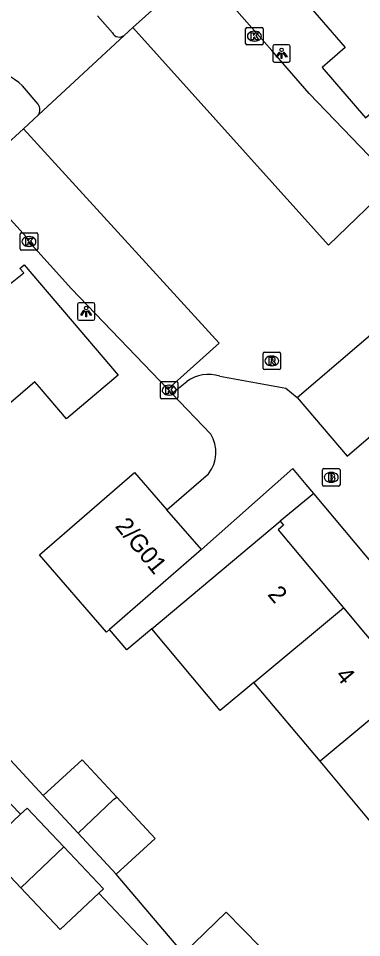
# Model space of a CAD drawing. Extents: x 157466 to 158888, y 383063 to 384677.
# Drawn here: x 158011.8 to 158031.4, y 383626.4 to 383679.1 of the extents above; entities that cross this region are included whole.
import ezdxf

# ---------------------------------------------------------------- set-up
doc = ezdxf.new("R2010")
doc.units = 0
for name, color, linetype in [('IMGEO_Brandkraan', 7, 'Continuous'), ('IMGEO_Kolk', 7, 'Continuous'), ('IMGEO_Lichtpunt', 7, 'Continuous'), ('IMGEO_Pand', 7, 'Continuous'), ('IMGEO_Pand_nummerreeks', 7, 'Continuous'), ('IMGEO_Parkeervlak_open', 7, 'Continuous'), ('IMGEO_Rijbaan_lokaal_open', 7, 'Continuous'), ('IMGEO_Rioolput', 7, 'Continuous'), ('IMGEO_Voetpad_open', 7, 'Continuous')]:
    doc.layers.add(name, color=color, linetype=linetype)

msp = doc.modelspace()

# ---------------------------------------------------------------- linework, layer by layer
at = {"layer": 'IMGEO_Brandkraan'}
for p, q in [((158029.199, 383652.369), (158029.199, 383653.221)), ((158029.274, 383653.295), (158030.126, 383653.295)), ((158029.687, 383653.075), (158029.712, 383653.075)), ((158030.2, 383653.221), (158030.2, 383652.369)), ((158029.71, 383652.515), (158029.685, 383652.515)), ((158030.126, 383652.295), (158029.274, 383652.295))]:
    msp.add_line(p, q, dxfattribs=at)
for points in [[(158029.199, 383652.369), (158029.199, 383653.221)], [(158029.274, 383653.295), (158030.126, 383653.295)], [(158029.547, 383652.995), (158029.547, 383652.595), (158029.76, 383652.595)], [(158029.778, 383652.995), (158029.547, 383652.995)], [(158030.2, 383653.221), (158030.2, 383652.369)], [(158029.726, 383652.914), (158029.672, 383652.914), (158029.672, 383652.838)], [(158029.672, 383652.838), (158029.725, 383652.838)], [(158029.734, 383652.762), (158029.672, 383652.762), (158029.672, 383652.681)], [(158029.672, 383652.681), (158029.734, 383652.681)], [(158030.126, 383652.295), (158029.274, 383652.295)]]:
    msp.add_lwpolyline(points, dxfattribs=at)
for centre, radius, start, end in [((158029.276, 383653.219), 0.0765, 91.552, 178.448), ((158029.276, 383653.219), 0.0765, 91.552, 178.448), ((158029.782, 383652.85), 0.145, 59.4692, 91.5367), ((158029.807, 383652.897), 0.0922, 285.5137, 58.1501), ((158030.124, 383653.219), 0.0765, 1.552, 88.448), ((158030.124, 383653.219), 0.0765, 1.552, 88.448), ((158029.727, 383652.876), 0.0379, 267.8285, 90.9355), ((158029.735, 383652.721), 0.0404, 269.8759, 90.5077), ((158029.766, 383652.846), 0.251, 268.6676, 293.5347), ((158029.812, 383652.705), 0.105, 301.3115, 78.989), ((158029.276, 383652.371), 0.0765, 181.552, 268.448), ((158029.276, 383652.371), 0.0765, 181.552, 268.448), ((158030.124, 383652.371), 0.0765, 271.552, 358.448), ((158030.124, 383652.371), 0.0765, 271.552, 358.448)]:
    msp.add_arc(centre, radius, start, end, dxfattribs=at)
for centre, major_axis, ratio, start_param, end_param in [((158029.686, 383652.795), (-0.387, 0.002), 0.722429, 4.712389, 7.853982), ((158029.711, 383652.795), (-0.39, 0.002), 0.717154, 1.570796, 4.712389)]:
    msp.add_ellipse(centre, major_axis=major_axis, ratio=ratio, start_param=start_param, end_param=end_param, dxfattribs=at)
at = {"layer": 'IMGEO_Kolk'}
for p, q in [((158024.794, 383677.639), (158024.794, 383678.491)), ((158024.869, 383678.565), (158025.721, 383678.565)), ((158025.282, 383678.345), (158025.307, 383678.345)), ((158025.795, 383678.491), (158025.795, 383677.639)), ((158025.305, 383677.785), (158025.28, 383677.785)), ((158025.721, 383677.565), (158024.869, 383677.565)), ((158011.88, 383665.877), (158011.88, 383666.729)), ((158011.955, 383666.803), (158012.807, 383666.803)), ((158012.881, 383666.729), (158012.881, 383665.877)), ((158012.368, 383666.583), (158012.393, 383666.583)), ((158012.807, 383665.803), (158011.955, 383665.803)), ((158012.391, 383666.023), (158012.366, 383666.023)), ((158019.908, 383657.361), (158019.908, 383658.213)), ((158019.983, 383658.287), (158020.835, 383658.287)), ((158020.909, 383658.213), (158020.909, 383657.361)), ((158020.396, 383658.067), (158020.421, 383658.067)), ((158020.835, 383657.287), (158019.983, 383657.287)), ((158020.419, 383657.507), (158020.394, 383657.507))]:
    msp.add_line(p, q, dxfattribs=at)
for points in [[(158024.794, 383677.639), (158024.794, 383678.491)], [(158024.869, 383678.565), (158025.721, 383678.565)], [(158025.115, 383678.265), (158025.238, 383678.265), (158025.238, 383678.114), (158025.368, 383678.265), (158025.532, 383678.265), (158025.386, 383678.114), (158025.539, 383677.865), (158025.387, 383677.865), (158025.302, 383678.029), (158025.238, 383677.962), (158025.238, 383677.865), (158025.115, 383677.865), (158025.115, 383678.265)], [(158025.795, 383678.491), (158025.795, 383677.639)], [(158025.721, 383677.565), (158024.869, 383677.565)], [(158011.88, 383665.877), (158011.88, 383666.729)], [(158011.955, 383666.803), (158012.807, 383666.803)], [(158012.881, 383666.729), (158012.881, 383665.877)], [(158012.201, 383666.503), (158012.324, 383666.503), (158012.324, 383666.352), (158012.454, 383666.503), (158012.618, 383666.503), (158012.472, 383666.352), (158012.625, 383666.103), (158012.473, 383666.103), (158012.388, 383666.267), (158012.324, 383666.2), (158012.324, 383666.103), (158012.201, 383666.103), (158012.201, 383666.503)], [(158012.807, 383665.803), (158011.955, 383665.803)], [(158019.908, 383657.361), (158019.908, 383658.213)], [(158019.983, 383658.287), (158020.835, 383658.287)], [(158020.909, 383658.213), (158020.909, 383657.361)], [(158020.229, 383657.987), (158020.352, 383657.987), (158020.352, 383657.836), (158020.482, 383657.987), (158020.646, 383657.987), (158020.5, 383657.836), (158020.653, 383657.587), (158020.501, 383657.587), (158020.416, 383657.751), (158020.352, 383657.684), (158020.352, 383657.587), (158020.229, 383657.587), (158020.229, 383657.987)], [(158020.835, 383657.287), (158019.983, 383657.287)]]:
    msp.add_lwpolyline(points, dxfattribs=at)
for centre, start, end in [((158024.871, 383678.489), 91.552, 178.448), ((158024.871, 383678.489), 91.552, 178.448), ((158025.719, 383678.489), 1.552, 88.448), ((158025.719, 383678.489), 1.552, 88.448), ((158024.871, 383677.641), 181.552, 268.448), ((158024.871, 383677.641), 181.552, 268.448), ((158025.719, 383677.641), 271.552, 358.448), ((158025.719, 383677.641), 271.552, 358.448), ((158011.957, 383666.727), 91.552, 178.448), ((158011.957, 383666.727), 91.552, 178.448), ((158012.805, 383666.727), 1.552, 88.448), ((158012.805, 383666.727), 1.552, 88.448), ((158011.957, 383665.879), 181.552, 268.448), ((158011.957, 383665.879), 181.552, 268.448), ((158012.805, 383665.879), 271.552, 358.448), ((158012.805, 383665.879), 271.552, 358.448), ((158019.985, 383658.211), 91.552, 178.448), ((158019.985, 383658.211), 91.552, 178.448), ((158020.833, 383658.211), 1.552, 88.448), ((158020.833, 383658.211), 1.552, 88.448), ((158019.985, 383657.363), 181.552, 268.448), ((158019.985, 383657.363), 181.552, 268.448), ((158020.833, 383657.363), 271.552, 358.448), ((158020.833, 383657.363), 271.552, 358.448)]:
    msp.add_arc(centre, 0.0765, start, end, dxfattribs=at)
for centre, major_axis, ratio, start_param, end_param in [((158025.281, 383678.065), (-0.387, 0.002), 0.722429, 4.712389, 7.853982), ((158025.306, 383678.065), (-0.39, 0.002), 0.717154, 1.570796, 4.712389), ((158012.367, 383666.303), (-0.387, 0.002), 0.722429, 4.712389, 7.853982), ((158012.392, 383666.303), (-0.39, 0.002), 0.717154, 1.570796, 4.712389), ((158020.395, 383657.787), (-0.387, 0.002), 0.722429, 4.712389, 7.853982), ((158020.42, 383657.787), (-0.39, 0.002), 0.717154, 1.570796, 4.712389)]:
    msp.add_ellipse(centre, major_axis=major_axis, ratio=ratio, start_param=start_param, end_param=end_param, dxfattribs=at)
at = {"layer": 'IMGEO_Lichtpunt'}
for p, q in [((158026.353, 383677.484), (158026.353, 383676.677)), ((158026.353, 383677.484), (158026.353, 383676.677)), ((158027.255, 383677.579), (158026.447, 383677.579)), ((158027.255, 383677.579), (158026.447, 383677.579)), ((158027.349, 383676.677), (158027.349, 383677.484)), ((158027.349, 383676.677), (158027.349, 383677.484)), ((158026.447, 383676.583), (158027.255, 383676.583)), ((158026.447, 383676.583), (158027.255, 383676.583)), ((158015.157, 383662.698), (158015.157, 383661.891)), ((158015.157, 383662.698), (158015.157, 383661.891)), ((158016.059, 383662.793), (158015.251, 383662.793)), ((158016.059, 383662.793), (158015.251, 383662.793)), ((158016.153, 383661.891), (158016.153, 383662.698)), ((158016.153, 383661.891), (158016.153, 383662.698)), ((158015.251, 383661.797), (158016.059, 383661.797)), ((158015.251, 383661.797), (158016.059, 383661.797))]:
    msp.add_line(p, q, dxfattribs=at)
for points in [[(158026.727, 383677.148), (158026.766, 383677.12), (158026.578, 383676.858), (158026.54, 383676.885), (158026.727, 383677.148)], [(158026.829, 383677.1), (158026.876, 383677.1), (158026.876, 383676.778), (158026.829, 383676.778), (158026.829, 383677.1)], [(158026.939, 383677.12), (158026.977, 383677.147), (158027.164, 383676.885), (158027.125, 383676.857), (158026.939, 383677.12)], [(158015.531, 383662.362), (158015.57, 383662.334), (158015.382, 383662.072), (158015.344, 383662.099), (158015.531, 383662.362)], [(158015.633, 383662.314), (158015.68, 383662.314), (158015.68, 383661.992), (158015.633, 383661.992), (158015.633, 383662.314)], [(158015.743, 383662.334), (158015.781, 383662.361), (158015.968, 383662.099), (158015.929, 383662.071), (158015.743, 383662.334)]]:
    msp.add_lwpolyline(points, dxfattribs=at)
for centre in [(158026.852, 383677.282), (158015.656, 383662.496)]:
    msp.add_circle(centre, 0.0994, dxfattribs=at)
for centre, start, end in [((158026.447, 383677.484), 90, 180), ((158026.447, 383677.484), 90, 180), ((158027.255, 383677.484), 0, 90), ((158027.255, 383677.484), 0, 90), ((158026.447, 383676.677), 180, 270), ((158026.447, 383676.677), 180, 270), ((158027.255, 383676.677), 270, 0), ((158027.255, 383676.677), 270, 360), ((158015.251, 383662.698), 90, 180), ((158015.251, 383662.698), 90, 180), ((158016.059, 383662.698), 0, 90), ((158016.059, 383662.698), 0, 90), ((158015.251, 383661.891), 180, 270), ((158015.251, 383661.891), 180, 270), ((158016.059, 383661.891), 270, 0), ((158016.059, 383661.891), 270, 360)]:
    msp.add_arc(centre, 0.0946, start, end, dxfattribs=at)
at = {"layer": 'IMGEO_Pand'}
for points in [[(158031.569, 383685.38), (158027.267, 383681.66), (158027.02, 383681.945), (158026.766, 383681.725), (158030.495, 383677.414), (158029.171, 383676.269), (158031.662, 383673.388), (158037.565, 383678.493)], [(158003.932, 383659.572), (158008.317, 383663.337), (158008.105, 383663.584), (158008.353, 383663.735), (158009.559, 383662.338), (158010.633, 383663.362), (158012.09, 383664.505), (158011.854, 383664.762), (158012.101, 383664.966), (158017.498, 383658.647), (158014.531, 383656.155), (158012.982, 383657.958), (158012.714, 383658.27), (158008.303, 383654.494)], [(158016.985, 383644.072), (158016.818, 383643.927), (158012.979, 383648.347), (158018.42, 383653.074), (158020.282, 383650.931)], [(158022.26, 383648.654), (158020.282, 383650.931)], [(158019.411, 383644.12), (158026.769, 383650.288)], [(158026.769, 383650.288), (158026.969, 383650.049), (158026.649, 383649.78), (158030.391, 383645.317)], [(158022.26, 383648.654), (158016.985, 383644.072)], [(158025.272, 383641.046), (158030.391, 383645.317)], [(158030.391, 383645.317), (158034.176, 383640.801)], [(158025.272, 383641.046), (158023.34, 383639.434), (158019.411, 383644.12)], [(158029.056, 383636.532), (158025.272, 383641.046)], [(158034.176, 383640.801), (158029.056, 383636.532)], [(158013.201, 383634.565), (158015.42, 383636.623), (158017.405, 383634.483)], [(158032.886, 383631.963), (158029.056, 383636.532)], [(158015.199, 383632.411), (158013.201, 383634.565)], [(158015.199, 383632.411), (158017.231, 383634.338), (158017.405, 383634.483)], [(158017.405, 383634.483), (158019.601, 383632.116), (158017.382, 383630.057)], [(158011.897, 383633.502), (158009.801, 383631.523), (158011.909, 383629.29)], [(158011.897, 383633.502), (158012.268, 383633.852), (158014.371, 383631.626)], [(158017.382, 383630.057), (158015.199, 383632.411)], [(158014.371, 383631.626), (158011.909, 383629.29)], [(158014.371, 383631.626), (158016.642, 383629.221), (158016.386, 383628.979)], [(158011.909, 383629.29), (158014.175, 383626.891), (158016.386, 383628.979)], [(158021.234, 383625.516), (158023.679, 383627.897), (158025.621, 383625.902)]]:
    msp.add_lwpolyline(points, dxfattribs=at)
at = {"layer": 'IMGEO_Parkeervlak_open'}
for points in [[(158033.301, 383669.722), (158028.432, 383674.777), (158026.297, 383677.24), (158022.137, 383681.981)], [(158020.339, 383657.837), (158014.816, 383663.599), (158012.381, 383666.302), (158012.232, 383666.546), (158009.061, 383670.029)]]:
    msp.add_lwpolyline(points, dxfattribs=at)
at = {"layer": 'IMGEO_Rijbaan_lokaal_open'}
for points in [[(158016.305, 383679.228), (158017.167, 383678.253)], [(158017.829, 383678.113), (158018.338, 383678.57)], [(158033.301, 383669.722), (158029.537, 383666.096), (158018.338, 383678.57)], [(158012.919, 383673.553), (158017.829, 383678.113)], [(158012.91, 383674.169), (158012.009, 383675.219)], [(158012.059, 383672.767), (158012.919, 383673.553)], [(158020.339, 383657.837), (158023.282, 383660.48), (158012.059, 383672.767)], [(158027.75, 383657.373), (158033.669, 383662.438)], [(158027.75, 383657.373), (158030.605, 383654.01), (158036.509, 383659.061), (158033.669, 383662.438)], [(158020.569, 383657.597), (158021.424, 383658.284)], [(158023.307, 383658.59), (158027.089, 383657.911), (158027.75, 383657.373)], [(158020.569, 383657.597), (158020.339, 383657.837)], [(158022.792, 383655.277), (158020.569, 383657.597)], [(158020.282, 383650.931), (158022.662, 383652.998)], [(158028.7, 383651.869), (158028.264, 383652.389), (158027.495, 383653.306), (158022.26, 383648.654)], [(158050.108, 383626.331), (158028.7, 383651.869)]]:
    msp.add_lwpolyline(points, dxfattribs=at)
for centre, radius, start, end in [((158017.551, 383678.435), 0.425, 205.3272, 310.7908), ((158009.964, 383673.189), 2.881, 44.801, 134.6074), ((158012.471, 383673.855), 0.54, 326.0463, 35.6278), ((158022.666, 383656.589), 2.102, 72.2383, 126.2222), ((158021.125, 383654.229), 1.969, 321.3057, 32.1648)]:
    msp.add_arc(centre, radius, start, end, dxfattribs=at)
at = {"layer": 'IMGEO_Rioolput'}
for p, q in [((158025.794, 383659.039), (158025.794, 383659.891)), ((158025.869, 383659.965), (158026.721, 383659.965)), ((158026.795, 383659.891), (158026.795, 383659.039)), ((158026.282, 383659.745), (158026.307, 383659.745)), ((158026.721, 383658.965), (158025.869, 383658.965)), ((158026.305, 383659.185), (158026.28, 383659.185))]:
    msp.add_line(p, q, dxfattribs=at)
for points in [[(158025.794, 383659.039), (158025.794, 383659.891)], [(158025.869, 383659.965), (158026.721, 383659.965)], [(158026.795, 383659.891), (158026.795, 383659.039)], [(158026.383, 383659.663), (158026.131, 383659.665), (158026.131, 383659.265)], [(158026.131, 383659.265), (158026.255, 383659.265), (158026.255, 383659.427), (158026.266, 383659.427)], [(158026.309, 383659.584), (158026.255, 383659.584), (158026.255, 383659.503)], [(158026.255, 383659.503), (158026.307, 383659.503)], [(158026.313, 383659.398), (158026.384, 383659.265), (158026.524, 383659.265), (158026.459, 383659.391)], [(158026.721, 383658.965), (158025.869, 383658.965)]]:
    msp.add_lwpolyline(points, dxfattribs=at)
for centre, radius, start, end in [((158025.871, 383659.889), 0.0765, 91.552, 178.448), ((158025.871, 383659.889), 0.0765, 91.552, 178.448), ((158026.719, 383659.889), 0.0765, 1.552, 88.448), ((158026.719, 383659.889), 0.0765, 1.552, 88.448), ((158026.265, 383659.374), 0.0533, 26.0293, 88.6989), ((158026.291, 383659.692), 0.19, 274.7715, 282.9687), ((158026.315, 383659.488), 0.0964, 77.0061, 93.1865), ((158026.329, 383659.545), 0.0378, 276.6634, 79.6772), ((158026.382, 383659.553), 0.109, 350.3612, 89.416), ((158026.38, 383659.553), 0.112, 277.5842, 350.9817), ((158026.364, 383659.338), 0.108, 29.5134, 73.7905), ((158025.871, 383659.041), 0.0765, 181.552, 268.448), ((158025.871, 383659.041), 0.0765, 181.552, 268.448), ((158026.719, 383659.041), 0.0765, 271.552, 358.448), ((158026.719, 383659.041), 0.0765, 271.552, 358.448)]:
    msp.add_arc(centre, radius, start, end, dxfattribs=at)
for centre, major_axis, ratio, start_param, end_param in [((158026.281, 383659.465), (-0.387, 0.002), 0.722429, 4.712389, 7.853982), ((158026.306, 383659.465), (-0.39, 0.002), 0.717154, 1.570796, 4.712389)]:
    msp.add_ellipse(centre, major_axis=major_axis, ratio=ratio, start_param=start_param, end_param=end_param, dxfattribs=at)
at = {"layer": 'IMGEO_Voetpad_open'}
for points in [[(158018.338, 383678.57), (158022.137, 383681.981)], [(158009.061, 383670.029), (158012.059, 383672.767)], [(158028.7, 383651.869), (158026.769, 383650.288)], [(158019.411, 383644.12), (158017.983, 383642.923), (158016.985, 383644.072)], [(158013.201, 383634.565), (158009.916, 383638.107), (158008.731, 383637.116)], [(157999.764, 383626.986), (158009.777, 383635.669), (158011.897, 383633.502)], [(158021.234, 383625.516), (158017.382, 383630.057)], [(158016.386, 383628.979), (158020.281, 383624.855)]]:
    msp.add_lwpolyline(points, dxfattribs=at)

# ---------------------------------------------------------------- texts
at = {"layer": 'IMGEO_Pand_nummerreeks'}
for s, rotation, p in [('2/G01', 309.2875, (158017.272, 383649.984)), ('2', 309.8427, (158026.013, 383646.072)), ('4', 309.8427, (158029.897, 383641.418))]:
    msp.add_text(s, height=1, rotation=rotation, dxfattribs=at).set_placement(p)

doc.saveas('drawing.dxf')
